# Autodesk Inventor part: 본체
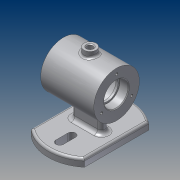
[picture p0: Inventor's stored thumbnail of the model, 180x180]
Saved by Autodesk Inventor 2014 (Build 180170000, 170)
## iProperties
Created: 2017-12
Part Number: 본체
Material: 알루미늄 6061
Document SubType Name: Modeling
Designer: user
Density: 2.71 g/cm^3
Appearance: 알루미늄 - 평지
Mass: 467.527 g
Surface Area: 486.931 cm^2
Volume: 172.519 cm^3
Author: user
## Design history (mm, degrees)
sketch "스케치1"
  geometry: L1 (35, -42.426)-(35, 42.426); L2 (-35, 42.426)-(-35, -42.426); L3 (-35, 42.426)-(35, 42.426); A1 r 55 centre (0, 0) between (-35, -42.426) and (35, -42.426); A2 r 55 centre (0, 0) between (35, 42.426) and (-35, 42.426); 2 further points
  constraints: 6 end point, 4 point on circle, 2 centre point, 1 coincident, 1 midpoint, 1 parallel, 1 perpendicular, 1 vertical alignment
  dimensions: "d2" = 70 distance between parallel lines of L1 L2; "d3" = 55 radius of A2; "d4" = 55 radius of A1
extrude "돌출1" new body sketch "스케치1" distance "d5" = 10; taper "d6" = 0 deg
sketch "스케치2"
  geometry: L1 (0, 40)-(0, 24); L2 (-5, 40)-(-5, 24); L3 (5, 24)-(5, 40); L4 (0, -24)-(0, -40); L5 (-5, -24)-(-5, -40); L6 (5, -40)-(5, -24); A1 r 5 centre (0, 40) between (5, 40) and (-5, 40); A2 r 5 centre (0, 24) between (-5, 24) and (5, 24); A3 r 5 centre (0, -24) between (5, -24) and (-5, -24); A4 r 5 centre (0, -40) between (-5, -40) and (5, -40); 3 further points
  constraints: 16 end point, 8 point on circle, 8 tangent, 4 centre point, 3 equal length, 2 midpoint, 2 vertical alignment, 1 vertical
  dimensions: "d7" = 16 distance of L1.start L1.end; "d8" = 10 diameter of A2; "d9" = 16 distance of L4.start L4.end; "d10" = 5 radius of A4; "d11" = 24 distance of point (0, 0) L4.start; "d12" = 24 distance of point (0, 0) L1.end
extrude "돌출2" cut sketch "스케치2" distance "d13" = 10; taper "d14" = 0 deg
sketch "스케치3"
  geometry: L1 (-67.128, 62)-(67.128, 62); C1 r 30 at (0, 62); 2 further points
  constraints: 2 end point, 1 centre point, 1 coincident, 1 horizontal, 1 midpoint, 1 vertical alignment
  dimensions: "d15" = 62 distance from line of point (0, 0) L1; "d17" = 60 diameter of C1
extrude "돌출3" join sketch "스케치3" stored distance "d18" = 70; taper "d19" = 0 deg
node "작업 평면1"
sketch "스케치4"
  geometry: C1 r 8 at (0, 0); 1 further point
  constraints: 1 centre point, 1 coincident
  dimensions: "d21" = 16 diameter of C1
extrude "돌출4" join sketch "스케치4" stored distance "d22" = 70; taper "d23" = 0 deg
sketch "스케치5"
  geometry: L1 (-15, 0)-(15, 0); L2 (-15, -5)-(15, -5); L3 (15, 5)-(-15, 5); A1 r 5 centre (-15, 0) between (-15, 5) and (-15, -5); A2 r 5 centre (15, 0) between (15, -5) and (15, 5); 1 further point
  constraints: 8 end point, 4 point on circle, 4 tangent, 2 centre point, 1 horizontal, 1 midpoint, 1 parallel
  dimensions: "d24" = 15 distance of point (0, 0) L1.end; "d25" = 10 diameter of A2
extrude "돌출5" join sketch "스케치5" stored distance "d26" = 70; taper "d27" = 0 deg
sketch "스케치6"
  geometry: L1 (-78.249, 62)-(81.995, 62); L2 (-35, 92)-(-35, 32) reference; L3 (-35, 62)-(-23, 62); L4 (-23, 62)-(-23, 78); L5 (-23, 78)-(-35, 78); L6 (-35, 78)-(-35, 62); L7 (-23, 62)-(-20, 62); L8 (-20, 62)-(-20, 76); L9 (-20, 76)-(-23, 76); L10 (-23, 76)-(-23, 62); L11 (-20, 62)-(20, 62); L12 (20, 62)-(20, 87); L13 (20, 87)-(-20, 87); L14 (-20, 87)-(-20, 62); L15 (20, 62)-(23, 62); L16 (23, 62)-(23, 76); L17 (23, 76)-(20, 76); L18 (20, 76)-(20, 62); L19 (23, 62)-(35, 62); L20 (35, 62)-(35, 78); L21 (35, 78)-(23, 78); L22 (23, 78)-(23, 62); 1 further point
  constraints: 42 end point, 10 parallel, 6 horizontal, 5 perpendicular, 1 midpoint
  dimensions: "d28" = 62 distance from line of point (0, 0) L1; "d29" = 12 distance of L5.end L4.end; "d30" = 16 distance of L4.end L3.end; "d31" = 3 distance of L9.end L8.end; "d32" = 14 distance of L8.end L7.end; "d33" = 40 distance of L13.end L12.end; "d34" = 25 distance of L12.end L11.end; "d35" = 3 distance of L17.end L16.end; "d36" = 14 distance of L16.end L15.end; "d37" = 12 distance of L21.end L20.end; "d38" = 16 distance of L20.end L19.end
revolve "회전1" sketch "스케치6" stored, may be unused: angle "d39" = 90 deg
hole "구멍1" diameter "d42" = 8; stored, may be unused: countersink angle "d46" = 90 deg, drill point angle "d48" = 118 deg; dims "d40" = 10, "d41" = 10, "d43" = 6, "d44" = 4, "d45" = 2, "d47" = 50
sketch "스케치7"
  geometry: C1 r 16 at (0, 0) reference; C2 r 30 at (0, 0) reference; 2 further points
  constraints: 1 horizontal alignment
  dimensions: "d49" = 23 distance of point (-23, 0) C1.centre
hole "구멍2" sketch "스케치7" at (-23, 0) diameter "d50" = 3.459; stored, may be unused: countersink angle "d54" = 90 deg, drill point angle "d56" = 118 deg; dims "d51" = 8, "d52" = 4, "d53" = 2, "d55" = 10
node "작업 평면2"
sketch "스케치9"
  geometry: L1 (-20, -82)-(50, -82) reference; 2 further points
  constraints: 1 vertical alignment, 1 other
  dimensions: "d61" = 30 distance from line of L1 point (15, -52)
feature "엠보싱1" sketch "스케치9" dims "d2" = 70, "d3" = 55, "d4" = 55, "d62" = 0.5, "d63" = 0
fillet "모깎기1" dims "d64" = 0.3
fillet "모깎기2" dims "d65" = 3
fillet "모깎기3" dims "d66" = 5
fillet "모깎기4" dims "d67" = 3
chamfer "모따기1" distance "d68" = 1; stored, may be unused: second distance "d69" = 2, angle "d70" = 45 deg
node "솔리드1"
pattern_circular "원형 패턴1" dims angle "d58" = 360 deg
mirror "대칭1"
node "투영된 루프1"
other parameters: "d20" = 89, "d60" = 58.5
